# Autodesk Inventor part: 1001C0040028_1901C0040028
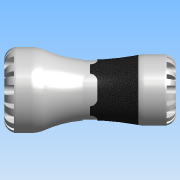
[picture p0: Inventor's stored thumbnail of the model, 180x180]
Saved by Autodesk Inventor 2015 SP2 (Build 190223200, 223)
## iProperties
Created: 2016-12
Part Number: 1001C0040028_1901C0040028
Material: PVC-Piping
Description: PLASSON COPPER PIPE ADAPTOR 40x28 SERIES 1
Document SubType Name: Modeling
Designer: KIM
Mass: 95.2094 g
Surface Area: 200.83 cm^2
Volume: 68.0067 cm^3
Density: 1.4 g/cm^3
Appearance: Smooth - White
ILogicFactory: False
Author: KIM
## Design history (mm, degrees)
derived "1001C.ipt"
feature "Solid1::1001C.ipt"
tag "TaggingFeature1"
body "Solid1"
other parameters: "d2" = 71, "d11" = 8, "d13" = 8, "d14" = 0, "d16" = 360 deg, "d18" = 8 deg, "d19" = 0.8, "d20" = 8 deg, "d21" = 0.8, "d23" = 0, "d25" = 360 deg, "d27" = 28, "d28" = 7.2, "d29" = 12, "d30" = 15.68, "d31" = 0, "d33" = 0, "d37" = 27.8, "d38" = 0.7, "d45" = 27.8, "d46" = 49.3, "d50" = 360 deg, "d54" = 0.513, "d60" = 28, "d62" = 58, "d63" = 27.8, "d64" = 139, "d65" = 55, "d66" = 2.33333, "d67" = 69.5, "d70" = 7.2, "d72" = 7.2, "d73" = 0, "d75" = 360 deg, "d77" = 8 deg, "d78" = 8 deg, "d79" = 0.8, "d80" = 0.8, "d82" = 0, "d84" = 360 deg, "H_" = 139, "l_" = 71, "d_1" = 28, "E_1" = 58, "l_1" = 55, "d68" = 58, "d71" = 9
